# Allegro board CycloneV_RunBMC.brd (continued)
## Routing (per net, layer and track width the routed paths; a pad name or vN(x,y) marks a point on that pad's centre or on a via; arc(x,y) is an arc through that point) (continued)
FP_ID_BTN_N: length 37.2
  TOP w0.104: v1(52.58,3.7) 52.61,3.7 52.94,3.37 52.94,2.9 52.93,2.88 JT3.199
  TOP w0.127: UT7.T12 v1(30.78,16.81)
  L3-SIG w0.076: v1(52.58,3.7) 52.28,3.7 52.09,3.51 52.09,2.95 51.76,2.62 49.13,2.62 48.98,2.77 48.98,3.9 49.17,4.1 49.17,6.28 45.56,9.89 45.56,11.69 44.37,12.88 41.65,12.88 41.32,13.21 39.39,13.21 39.19,13.01 39.19,12.62 39.01,12.44 36.21,12.44 35.92,12.72 35.92,14.75 35.1,15.58 31.34,15.58 31.2,15.72 31.2,16.39 v1(30.78,16.81)
  L3-SIG w0.089: v1(30.78,16.81) 30.74,16.81
FP_ID_LED_N: length 16
  TOP w0.089: UT7.AH2 v1(39.58,9.61)
  BOTTOM w0.089: 33.63,7.65 33.63,8.15 33.86,8.39 34.18,8.39 34.43,8.63 34.43,8.95 34.63,9.16 38.12,9.16 38.12,9.16 39.13,9.16 v1(39.58,9.61)
  BOTTOM w0.112: 33.63,7.65 33.63,7.12 33.34,6.83 32.14,6.83 32.05,6.74 32.05,6.05 32.21,5.89 RB179.2 32.53,5.81 32.53,5.03 31.54,4.04 31.54,2.95 31.68,2.81 JT3.122
FP_LED_STATUS_AMBER_N: length 28.4
  TOP w0.127: UT7.T13 v1(30.78,17.61)
  L5-SIG w0.076: v1(30.78,17.61) 31.18,18.01 31.79,18.01 31.97,17.84 31.97,16.52 32.23,16.26 32.23,15.83 31.18,14.79 31.18,13.14 29.48,11.44 29.48,7.04 28.32,5.88 28.32,4.86 28.68,4.49 28.69,4.49 28.9,4.28 28.9,3.18 29.32,2.76 30.08,2.76 30.27,2.95 30.27,3.49 30.57,3.79 31.3,3.79 32.16,4.65 32.58,4.65 v1(32.73,4.5)
  BOTTOM w0.112: JT3.124 32.18,2.8 32.35,2.98 32.35,3.63 32.36,3.63 32.36,4.13 v1(32.73,4.5) 32.73,4.86 32.96,5.09 RB182.2
FP_LED_STATUS_GREEN_N: length 10.3
  TOP w0.127: v1(40.36,9.63) UT7.AH3
  BOTTOM w0.089: v1(40.36,9.63) 40.43,9.56 RB154.2
  BOTTOM w0.112: RB154.2 40.43,8.62 40.56,8.49 41.75,8.49 42.13,8.11 42.13,4.91 42.46,4.58 42.46,2.93 42.68,2.71 JT3.158
FP_NMI_BTN_N: length 29.1
  TOP w0.104: v1(51.27,3.85) 51.63,3.49 51.63,3.08 51.43,2.88 JT3.193
  TOP w0.127: UT7.AF11 v1(38.78,16.01)
  L3-SIG w0.076: v1(38.78,16.01) 39.14,15.64 39.89,15.64 40.2,15.95 40.72,15.95 42.44,14.23 44.57,14.23 45.28,13.52 49.93,13.52 50.31,13.9 51.56,13.9 51.86,13.59 51.86,12.91 52.46,12.31 52.46,9.07 52.47,9.06 52.47,9.05 52.52,9 52.52,6.58 52.28,6.35 52.28,5.6 52.1,5.42 51.2,5.42 50.89,5.11 50.89,4.22 v1(51.27,3.85)
FP_PWR_BTN_N: length 13.9
  TOP w0.127: UT7.AF5 v1(38.78,11.21)
  BOTTOM w0.112: v1(38.78,11.21) 39.16,10.83 39.16,10.1 39.27,9.99 40.79,9.99 40.8,9.98 41.88,9.98 42.37,9.49 42.37,5.87 43.55,4.69 43.55,3.7 43.33,3.47 43.33,2.82 43.18,2.68 JT3.160
FP_RST_BTN_N: length 22.6
  TOP w0.104: v1(31.97,3.79) 31.7,3.52 31.57,3.52 31.43,3.37 JT3.121
  TOP w0.127: UT7.AF10 v1(38.78,15.21)
  L8-SIG w0.076: v1(31.97,3.79) 31.97,4.18 32,4.2 32,4.83 32.73,5.57 32.73,6.18 33,6.44 35.82,6.44 37.39,8.02 40.04,8.02 41.35,9.33 41.35,10.53 39.97,11.91 39.97,12.98 39.16,13.79 39.16,14.83 v1(38.78,15.21)
IRQ_BMC_PCH_NMI: length 24.4
  TOP w0.127: UT7.C14 v1(19.58,18.41)
  L8-SIG w0.076: v1(19.58,18.41) 19.17,18.81 16.54,18.81 14.83,17.1 14.83,16.62 12.08,13.87 12.08,10.24 11.4,9.56 11.4,7.75 10.29,6.64 10.29,5.02 11.01,4.3 11.14,4.3 v1(11.37,4.07)
  BOTTOM w0.112: v1(11.37,4.07) 11.45,4.07 11.78,3.74 11.78,3.18 11.68,3.08 JT3.42
IRQ_BMC_PCH_SCI_LPC_R_N: length 30.5
  TOP w0.127: UT7.J16 v1(24.38,20.81)
  L8-SIG w0.076: v1(12.36,3.85) 12.08,4.12 11.88,4.33 11.88,5.24 12.27,5.63 12.27,6.85 11.88,7.24 11.88,9.33 12.58,10.03 12.58,11.88 13.73,13.04 14.65,13.04 15.44,13.82 15.44,14.81 17.85,17.23 20.59,17.23 21.79,18.43 21.79,18.9 23.25,20.37 23.94,20.37 v1(24.38,20.81)
  BOTTOM w0.112: JT3.44 12.18,2.98 12.09,3.07 12.09,3.58 v1(12.36,3.85)
  BOTTOM w0.114: v1(12.36,3.85) 12.08,4.12 11.83,4.38 11.83,5.03 12.17,5.37 12.25,5.37 12.36,5.48 RB73.2
IRQ_BMC_PCH_SMI_LPC_N: length 30.6
  TOP w0.127: UT7.AF23 v1(38.78,26.41)
  L5-SIG w0.076: v1(41.6,7.49) 41.89,7.78 41.89,10.38 41.34,10.93 41.34,11.21 41.95,11.82 41.95,13.9 41.32,14.53 41.32,18.93 42.42,20.03 42.42,21.44 41.52,22.33 41.52,24.34 40.62,25.25 40.23,25.25 40.02,25.46 40.02,25.9 39.87,26.04 39.15,26.04 v1(38.78,26.41)
  BOTTOM w0.089: RB72.2 39.49,27.03 39.22,26.76 39.13,26.76 v1(38.78,26.41)
  BOTTOM w0.112: v1(41.6,7.49) 40.98,6.87 40.98,5.29 41.11,5.15 41.11,5.15 41.9,4.36 41.9,3.11 41.68,2.88 JT3.154
IRQ_L_PIRQA_N_E_ALERT0_N_BMC: length 18.2
  TOP w0.104: JT3.171 45.93,3.27 45.33,3.87 44.75,3.87 v1(44.73,3.89)
  TOP w0.127: UT7.AA4 v1(34.78,10.41)
  L3-SIG w0.076: v1(34.78,10.41) 35.17,10.01 35.17,8.72 35.5,8.39 36.04,8.39 36.85,7.57 40.94,7.57 41.23,7.86 41.76,7.86 42.05,7.57 42.05,6.47 42.67,5.85 43.02,5.85 44.25,4.62 44.25,4.37 v1(44.73,3.89)
IRQ_NMI_EVENT_N: length 23.3
  TOP w0.127: UT7.B14 v1(18.78,18.41)
  L3-SIG w0.076: v1(12.35,4.41) 12.61,4.67 12.61,4.7 12.74,4.83 12.74,4.88 13.71,5.85 13.71,6.99 14.11,7.39 14.11,8.84 14.03,8.92 14.03,11.4 13.81,11.62 13.81,12.78 13.98,12.95 13.98,14.43 14.17,14.62 14.17,14.99 13.88,15.28 13.88,17.48 14.13,17.73 14.68,17.73 14.83,17.58 15.31,17.58 15.72,17.99 18.36,17.99 v1(18.78,18.41)
  BOTTOM w0.112: v1(12.35,4.41) 12.74,4.02 12.74,4.02 12.75,4.01 12.75,3.69 12.93,3.51 12.93,3.5 12.93,3.5 12.93,3.18 12.68,2.92 JT3.46
IRQ_SMB_INTERNAL_ALERT_N: length 21.8
  TOP w0.114: 19.58,21.61 v1(19.58,21.62)
  TOP w0.127: UT7.C17 19.58,21.61
  L3-SIG w0.076: v1(19.58,21.62) 19.17,22.03 19.17,22.54 18.92,22.79 18.43,22.79 18.21,22.56 18.21,22.38 17.74,21.92 16.93,21.92 16.17,21.16 16.17,19.87 15.89,19.58 14.01,19.58 12.13,17.71 12.13,16.36 10.31,14.53 10.31,13.57 v1(9.9,13.16)
  BOTTOM w0.114: v1(9.9,13.16) 9.63,12.89 9.63,12.81 8.87,12.06 RB140.1 ; RB88.1 18.39,21.97 19.23,21.97 v1(19.58,21.62)
IRQ_SMB_INTERNAL_ALERT_R_N: length 9.1
  TOP w0.104: EUT2.6 7.63,10.12 8.08,10.57 8.08,10.83 8.2,10.96 v1(8.2,10.98) 8.48,11.25 8.49,11.25 8.78,11.54 10.18,11.54 10.31,11.66 10.94,11.66 11.25,11.36 12.31,11.36 12.61,11.66 13.54,11.66 13.81,11.93 EUT1.22
  BOTTOM w0.112: RB140.2 7.7,11.08 8.1,11.08 v1(8.2,10.98)
IRQ_SMI_ACTIVE_N: length 50.6
  TOP w0.127: v1(41.03,27.48) 41.03,27.22 40.88,27.08 40.33,27.08 40.2,27.21 39.58,27.21 UT7.AG24
  L8-SIG w0.076: v1(15.39,5.82) 15.39,5.83 15.71,6.16 15.71,9.1 16.12,9.51 17.24,9.51 17.52,9.78 17.52,13.85 18.51,14.84 18.94,14.84 18.94,14.84 19.78,14.84 19.96,15.02 19.96,15.32 20.21,15.58 20.57,15.58 20.77,15.77 20.77,16.54 23.31,19.08 25.65,19.08 26.38,19.82 26.38,23.09 27.22,23.93 27.22,24.16 27.5,24.45 27.73,24.45 28.01,24.73 28.01,25.05 28.44,25.48 34.89,25.48 35.38,25.96 35.71,25.96 36.54,26.8 40.3,26.8 40.6,27.1 40.65,27.1 41.02,27.48 v1(41.03,27.48)
  BOTTOM w0.112: JT3.70 18.68,4.18 17.77,5.09 17.05,5.09 16.31,5.82 v1(15.39,5.82)
IRQ_SML0_ALERT_N: length 34.8
  TOP w0.127: UT7.B18 v1(18.78,22.41)
  L3-SIG w0.076: v1(17.37,4.7) 17.37,3.67 16.94,3.24 16.94,3.23 16.38,2.67 12.68,2.67 11.97,3.38 11.97,5.41 11.99,5.42 11.99,7.84 12.5,8.34 12.5,12.13 13.15,12.78 13.15,14.1 13,14.25 13,15.22 13.43,15.65 13.43,17.91 14.55,19.03 16.12,19.03 16.83,19.74 16.83,20.17 17.77,21.11 18.23,21.11 18.38,21.27 18.38,22.01 v1(18.78,22.41)
  BOTTOM w0.112: v1(17.37,4.7) 17.77,4.3 17.77,2.95 17.65,2.83 17.65,1.61 JT3.66
  BOTTOM w0.114: v1(18.78,22.41) 18.81,22.44 RB95.1
IRQ_SML1_PMBUS_ALERT_N: length 39.4
  TOP w0.089: UT7.AG15 39.53,19.26 40.25,19.26 40.38,19.39
  TOP w0.104: 40.38,19.39 41.22,20.22 RT57.1
  TOP w0.114: v1(41.5,20.86) 41.36,20.72 RT57.1
  L8-SIG w0.076: v1(19.5,4.88) 19.5,5.4 20.24,6.14 21.02,6.14 21.07,6.19 21.52,6.64 22,6.64 23.39,8.03 23.39,8.87 24.5,9.99 24.66,9.99 24.82,10.15 24.82,10.56 25.04,10.79 29.27,10.79 29.56,11.08 29.56,11.3 30.71,12.45 31.41,12.45 32.15,13.19 32.47,13.19 32.74,13.46 32.74,13.83 32.94,14.03 33.31,14.03 33.54,14.26 33.54,14.65 33.72,14.84 34.12,14.84 34.34,15.06 34.34,15.63 34.59,15.88 35.2,15.88 35.9,16.58 35.9,17.37 36.49,17.96 37.02,17.96 37.03,17.97 40.87,17.97 41.5,18.6 v1(41.5,20.86)
  BOTTOM w0.112: JT3.74 19.68,2.88 19.93,3.13 19.93,4.46 v1(19.5,4.88)
ISENSE_P3V3_C: length 0.5
  BOTTOM w0.112: RB161.2 CB210.1
ISENSE_P3V3_N: length 1.2
  TOP w0.104: RT101.2 8.22,9.17 7.93,9.47 EUT2.5
ISENSE_P3V3_P: length 1.3
  TOP w0.104: EUT2.4 6.71,8.65 6.97,8.39 v1(7.08,8.39)
  BOTTOM w0.112: v1(7.08,8.39) 7.03,8.34 6.51,8.34 CB210.2
ISENSE_P12V_C: length 0.6
  TOP w0.104: CT25.1 RT134.2
ISENSE_P12V_N: length 3
  TOP w0.104: v1(4.79,7.87) 4.79,8 4.58,8.21 EUT2.1
  BOTTOM w0.112: RB171.2 5.19,6.37 4.79,6.76 v1(4.79,7.87)
ISENSE_P12V_P: length 2.7
  TOP w0.104: CT25.2 3.45,7.37 3.27,7.55 3.27,8.62 3.77,9.11 EUT2.16
JTAG_C5_FPGA_TCK: length 60.2
  TOP w0.127: UT7.AB5 v1(35.58,11.21)
  L3-SIG w0.076: v1(59.15,47.4) 59.15,47.03 58.56,46.44 49.5,46.44 48.74,45.67 v1(46.35,45.67)
  L5-SIG w0.076: v1(35.58,11.21) 36.04,11.21 36.77,11.94 36.77,18.85 37.54,19.62 37.54,23.58 38.34,24.38 38.34,26.48 38.66,26.8 43.25,26.8 45.61,29.16 45.61,30.4 46.55,31.35 46.55,36.05 46.11,36.49 46.11,37.99 46.75,38.64 46.75,44.88 46.35,45.29 v1(46.35,45.67)
  BOTTOM w0.112: v1(59.15,47.4) 59.15,47.84 59,47.99 CB22.1 RB48.1 57.78,47.99 57.7,47.91 57.7,47.24 57.63,47.17 U12.4
JTAG_C5_FPGA_TDI: length 54.2
  TOP w0.127: UT7.W10 v1(33.18,15.21)
  L8-SIG w0.076: v1(33.18,15.21) 34.08,16.11 34.79,16.11 35.43,16.74 35.43,17.64 36.57,18.78 40.79,18.78 41.04,19.03 41.04,21.03 41.43,21.42 44.18,21.42 45.92,23.16 45.92,28.17 47.01,29.27 47.01,31.27 49.07,33.33 49.07,41.76 50.36,43.06 60.19,43.06 61.03,43.9 v1(61.03,45.09)
  BOTTOM w0.112: 59.78,44.21 U12.9 RB49.2 CB33.1 60.69,44.72 61.03,45.07 v1(61.03,45.09)
JTAG_C5_FPGA_TDO: length 46.5
  L8-SIG w0.076: v1(42.87,17.63) 42.87,18.34 43.73,19.21 43.73,20.3 46.2,22.76 46.2,28.05 49.37,31.22 49.37,39.44 50.91,40.98 58.28,40.98 v1(58.57,40.7)
  BOTTOM w0.112: v1(58.57,40.7) 58.72,40.85 58.72,42.3 58.48,42.54 CT7.1 58.13,43.3 U12.12 ; v1(42.87,17.63) 42.6,17.36 42.6,17.2 42.5,17.1 40.3,17.1 40,17.4 38.29,17.4 38.11,17.23 36.75,17.23 36.47,16.95 36.47,15.13 RB123.1
JTAG_C5_FPGA_TDO_R: length 2.5
  TOP w0.127: UT7.Y9 33.96,14.43 v1(33.98,14.43)
  BOTTOM w0.089: RB123.2 35.36,14.84 34.38,14.84 33.98,14.43 v1(33.98,14.43)
JTAG_C5_FPGA_TDO_SW: length 11.4
  L10-SIG w0.076: v1(52.43,45.62) 52.43,46 52.35,46.08 51.71,46.08 51.5,45.88 51.5,43.67 52.62,42.55 v1(57.19,42.55)
  BOTTOM w0.112: UB2.3 v1(52.43,45.62) ; U12.14 57.13,42.61 v1(57.19,42.55)
JTAG_C5_FPGA_TMS: length 65
  TOP w0.127: UT7.AC7 v1(36.38,12.81)
  L3-SIG w0.076: v1(51.15,12.66) 48.76,12.66 48.38,13.04 48.19,13.04 48.06,12.91 48.06,12.6 47.82,12.36 47.47,12.36 47.25,12.58 47.25,12.71 46.92,13.04 45,13.04 44.52,13.52 42.16,13.52 41.26,14.42 40.27,14.42 39.86,14.01 36.99,14.01 36.77,13.8 36.77,13.2 v1(36.38,12.81)
  L8-SIG w0.076: v1(51.15,12.66) 51.48,12.66 51.66,12.83 51.66,14.1 50.6,15.16 50.6,21.2 50.15,21.65 50.15,24.95 49.93,25.18 49.93,30.3 50.87,31.23 50.87,37.67 51.25,38.05 59.07,38.05 61.18,40.16 v1(61.18,40.82)
  BOTTOM w0.112: v1(61.18,40.82) 61.18,41.71 61.56,42.09 61.56,44.94 61.56,44.94 61.56,45.26 61.56,45.26 61.56,46.11 61.37,46.3 CB23.1 RB46.2 60.46,46.82 59.2,46.82 59.13,46.75 U12.7
JTAG_HDR_SW_TCK: length 2.3
  TOP w0.104: v1(56.61,47.38) 56.61,47 56.74,46.87 RB52.2
  BOTTOM w0.112: U12.2 56.63,47.31 56.61,47.33 v1(56.61,47.38)
JTAG_HDR_SW_TMS: length 14.7
  L5-SIG w0.076: v1(52.37,39.48) 53.82,40.92 54.62,40.92 55.11,41.42 55.11,44.23 55.63,44.74 55.63,47.81 55.86,48.05 57.82,48.05 58.08,47.78 v1(58.08,47.38)
  BOTTOM w0.112: v1(52.37,39.48) 52.58,39.69 RB26.2 ; U12.5 58.13,47.33 v1(58.08,47.38)
JTAG_HDR_TCK: length 12.6
  TOP w0.104: J8.1 50.26,41.31 50.56,41 55.87,41 56.45,41.57 56.45,42.59 56.15,42.88 56.15,43.97 56.34,44.16 RB51.1 RB52.1
JTAG_HDR_TDI: length 2.7
  TOP w0.104: J8.9 55.34,41.64 v1(55.54,41.43)
  BOTTOM w0.112: v1(55.54,41.43) 55.54,40.72 RB22.1
JTAG_HDR_TDO: length 9.8
  TOP w0.104: v1(51.66,41.51) 51.53,41.64 J8.3
  L5-SIG w0.076: v1(51.9,45.6) 51.9,41.95 51.66,41.71 v1(51.66,41.51)
  BOTTOM w0.112: v1(51.9,45.6) 51.9,45.98 51.86,46.02 51.86,48.09 52.01,48.24 UB2.4 ; CB51.1 v1(51.66,41.51)
JTAG_HDR_TMS: length 3.6
  TOP w0.104: v1(52.77,41.43) 52.8,41.46 J8.5
  BOTTOM w0.112: v1(52.77,41.43) 53.03,41.18 RB26.1 RB28.1
JTAG_HPS_TCK: length 33.1
  TOP w0.104: v1(11.07,40.11) 11.3,40.11 11.85,40.67 11.85,40.74 12.58,41.47 RT1.1 12.64,41.76 12.89,42.01 J4.4
  TOP w0.127: UT7.K19 25.18,23.21 v1(25.16,23.21)
  L10-SIG w0.076: v1(25.16,23.21) 25.16,23.38 24.78,23.75 24.78,24.09 24.48,24.39 23.26,24.39 23.18,24.31 21.86,24.31 21.56,24.62 21.56,24.91 21.27,25.2 20.95,25.2 20.8,25.35 20.8,27.29 20.44,27.64 17.21,27.64 15.11,29.75 15.11,33.3 13.76,34.65 13.76,39.45 13.28,39.93 13.1,39.93 12.31,40.72 11.68,40.72 v1(11.07,40.11)
JTAG_HPS_TDI: length 28.1
  TOP w0.104: 10.48,41.46 10.35,41.59 J4.8 ; 10.48,41.46 10.71,41.46 v1(11.04,41.79) ; 10.48,41.46 RT3.2
  TOP w0.127: UT7.D22 v1(20.38,25.61)
  L10-SIG w0.076: v1(20.38,25.61) 20,25.99 17.57,25.99 16.86,26.69 16.84,26.69 14.4,29.14 13.84,29.14 13.35,29.62 13.35,31.83 13.15,32.03 12.85,32.03 12.39,32.49 12.39,32.75 12.16,32.97 9.72,32.97 9.47,33.23 9.47,33.74 9.59,33.86 9.59,38.11 10,38.51 10,40.75 v1(11.04,41.79)
JTAG_HPS_TDO: length 23.8
  TOP w0.104: v1(11.04,41.23) 11.26,41.45 RT4.2 11.54,41.79 11.62,41.87 J4.6
  TOP w0.127: v1(17.87,26.45) 17.91,26.41 18.77,26.41 UT7.B23
  L10-SIG w0.076: v1(11.04,41.23) 10.99,41.23 10.43,40.67 10.43,34.13 10.62,33.94 11.47,33.94 11.95,33.46 12.64,33.46 13.56,32.54 13.56,29.83 13.79,29.6 14.37,29.6 17.52,26.45 v1(17.87,26.45)
JTAG_HPS_TMS: length 23.9
  TOP w0.104: v1(11.98,39.76) 12.92,39.76 13.54,40.38 13.54,41.19 13.71,41.36 14.29,41.36 14.38,41.45 RT5.2 14.54,42.1 14.16,42.48 J4.2
  TOP w0.127: UT7.C23 v1(19.58,26.41)
  L10-SIG w0.076: v1(19.58,26.41) 19.13,26.85 17.54,26.85 14.83,29.57 14.83,33 13.57,34.26 13.57,38.17 v1(11.98,39.76)
JTAG_M10_MASTER_TCK: length 1
  BOTTOM w0.112: U12.3 57.13,47.49 RB54.2
JTAG_M10_MASTER_TCK_R: length 19.4
  TOP w0.127: UT4.K11 v1(53.39,33.53)
  L5-SIG w0.076: v1(53.39,33.53) 52.9,34.02 52.9,39.15 53.74,39.99 55.39,39.99 56.51,41.1 56.51,43.31 56.08,43.74 v1(56.08,47.5)
  BOTTOM w0.112: v1(56.08,47.5) 56.08,48.08 56.53,48.53 57.16,48.53 RB54.1
JTAG_M10_MASTER_TDI: length 19.1
  L3-SIG w0.076: v1(51.38,39.5) 51.81,39.93 51.81,40.85 51.96,41 55.67,41 56.41,40.26 59.43,40.26 v1(59.81,40.65)
  BOTTOM w0.112: v1(51.38,39.5) 50.92,39.05 50.92,35.21 50.77,35.06 50.09,35.06 RB70.2 ; v1(59.81,40.65) 59.58,40.87 59.58,41.07 59.58,41.07 59.58,42.29 59.13,42.74 U12.10
JTAG_M10_MASTER_TDI_R: length 1.6
  TOP w0.127: UT4.K14 v1(50.42,33.55)
  BOTTOM w0.112: v1(50.42,33.55) 49.62,33.55 RB70.1
JTAG_M10_MASTER_TDO: length 12.1
  TOP w0.127: UT4.L11 v1(53.39,34.52)
  L5-SIG w0.076: v1(57.19,41.43) 57.19,38.94 56.28,38.03 55.11,38.03 54.81,37.72 54.81,36.2 54.58,35.97 54.2,35.97 53.99,35.77 53.99,35.13 v1(53.39,34.52)
  BOTTOM w0.112: U12.13 57.63,41.87 v1(57.19,41.43)
JTAG_M10_MASTER_TMS: length 27.4
  L5-SIG w0.076: v1(52.42,37.57) 51.8,38.19 51.8,39.96 51.67,40.09 50.95,40.09 50.59,40.44 50.59,47.86 51.17,48.44 58.26,48.44 58.62,48.09 v1(58.62,47.38)
  BOTTOM w0.112: U12.6 58.63,47.36 v1(58.62,47.38) ; RB55.2 52.75,32.11 52.93,32.29 52.93,36.71 52.42,37.22 v1(52.42,37.57)
JTAG_M10_MASTER_TMS_R: length 1.2
  TOP w0.127: UT4.K12 v1(52.42,33.56)
  BOTTOM w0.112: RB55.1 52.42,33.02 v1(52.42,33.56)
JTAG_M10_TCK: length 15.5
  TOP w0.104: RB51.2 RB53.1 CB55.1 58.21,42.07 58.72,41.56 58.72,41.15 v1(59.2,40.67) ; UT4.H3 v1(62.29,32.43)
  L10-SIG w0.076: v1(62.29,32.43) 62.76,32.89 62.76,36.48 61.69,37.55 60.78,37.55 59.2,39.12 v1(59.2,40.67)
JTAG_M10_TDI: length 18.5
  TOP w0.104: UT4.G1 63.93,31.07 64.51,31.07 64.64,31.2 v1(64.81,31.2)
  L10-SIG w0.076: v1(56.33,39.5) 57.98,39.5 60.88,36.61 60.88,31.4 61.41,30.87 64.48,30.87 v1(64.81,31.2)
  BOTTOM w0.112: v1(56.33,39.5) 56.03,39.81 RB22.2 55.42,39.65 RB24.2 CB2.1
JTAG_M10_TDO: length 28
  TOP w0.104: RT48.2 v1(67.37,31.65)
  L10-SIG w0.076: v1(52.43,45.09) 52.43,44.65 53.43,43.64 64.15,43.64 64.83,42.96 64.83,35.9 65.55,35.18 65.55,32.37 66.26,31.65 v1(67.37,31.65)
  BOTTOM w0.112: UB3.4 v1(52.43,45.09)
JTAG_M10_TDO_BYPASS: length 6.1
  L5-SIG w0.076: v1(53.96,41.48) 53.96,44.97 53.71,45.21 v1(53.71,45.6)
  BOTTOM w0.112: UB3.1 53.73,41.71 v1(53.96,41.48) ; UB2.1 53.74,46.45 53.74,45.62 v1(53.71,45.6)
JTAG_M10_TDO_R: length 2.2
  TOP w0.104: UT4.H1 65.58,32.02 RT48.1
JTAG_M10_TDO_SW: length 10.6
  L10-SIG w0.076: v1(59.18,41.26) 58.51,41.26 58.26,41 52.65,41 v1(52.22,41.43)
  BOTTOM w0.112: v1(59.18,41.26) 59.2,41.28 59.2,42.17 58.63,42.74 U12.11 ; UB3.3 52.43,41.65 v1(52.22,41.43)
JTAG_M10_TMS: length 18.1
  TOP w0.104: UT4.H2 v1(63.35,32.49)
  L10-SIG w0.076: v1(63.35,32.49) 62.85,31.98 62.05,31.98 61.83,32.2 61.83,36.77 61.46,37.14 60.8,37.14 57.93,40.01 54.86,40.01 v1(54.35,39.5)
  BOTTOM w0.112: CB17.1 RB33.2 53.64,39.59 RB28.2 54.16,39.69 v1(54.35,39.5)
LED_AMBER_C: length 1.6
  TOP w0.104: DST2.C 67.66,36.95 67.13,36.42 67.13,36.1 RT32.1
LED_AMBER_R: length 1.7
  TOP w0.104: RT32.2 66.74,34.14 66.82,34.07 v1(66.82,34.02)
  BOTTOM w0.112: QB1.6 v1(66.82,34.02)
LED_GREEN_C: length 1.5
  TOP w0.104: RT31.1 66.01,36.86 DST1.2
LED_GREEN_R: length 2.9
  TOP w0.104: v1(64.92,34.57) 65.31,34.57 65.57,34.83 RT31.2
  BOTTOM w0.112: QB1.3 65.52,33.41 64.92,34.01 v1(64.92,34.57)
LPC_CLK_24M_66M_LPC0_ESPI_BMC: length 28.8
  TOP w0.104: v1(48.33,3.66) 48.2,3.66 47.89,3.35 47.89,1.62 JT3.179
  TOP w0.127: UT7.U9 31.58,14.41 v1(31.58,13.61)
  L3-SIG w0.076: v1(48.33,3.66) 48.33,6.77 47.26,7.84 46.22,7.84 45.57,8.49 44.31,8.49 42.68,10.12 42.68,11.2 42,11.87 40.56,11.87 39.55,10.86 36.56,10.86 35.87,11.55 35.55,11.55 35.17,11.93 35.17,12.45 34.46,13.16 34.46,13.6 34.06,14 31.97,14 v1(31.58,13.61)
LPC_LAD0_ESPI_IO0_BMC: length 22.1
  TOP w0.104: v1(44.7,4.55) 44.34,4.19 44.34,3.68 44.51,3.51 45.18,3.51 45.43,3.26 JT3.169
  TOP w0.127: UT7.W8 v1(33.17,13.62)
  L3-SIG w0.076: v1(44.7,4.55) 44.53,4.72 44.51,4.72 43.1,6.13 42.79,6.13 42.39,6.53 42.39,7.58 41.63,8.34 40.2,8.34 39.87,8.01 36.69,8.01 35.96,8.73 35.96,9.72 35.67,10.01 35.48,10.01 35.17,10.32 35.17,10.51 34.85,10.83 34.67,10.83 34.38,11.11 34.38,11.3 33.17,12.51 v1(33.17,13.62)
LPC_LAD1_ESPI_IO1_BMC: length 18.6
  TOP w0.104: v1(45.02,3.12) 44.93,3.03 JT3.167
  TOP w0.127: UT7.Y4 v1(33.98,10.41)
  L3-SIG w0.076: v1(45.02,3.12) 44.6,3.12 43.66,4.07 43.66,4.45 42.84,5.26 42.56,5.26 41.44,6.39 41.44,6.39 41.29,6.53 36.87,6.53 36.06,7.35 33.9,7.35 33.63,7.62 33.63,10.06 v1(33.98,10.41)
LPC_LAD2_ESPI_IO2_BMC: length 18.1
  TOP w0.104: JT3.177 47.43,3.35 46.71,4.07 v1(46.32,4.07)
  TOP w0.127: UT7.AB4 v1(35.58,10.41)
  L3-SIG w0.076: v1(46.32,4.07) 45.95,4.07 45.09,4.93 45.03,4.93 45.02,4.93 44.6,4.93 43.2,6.33 43.02,6.33 42.62,6.73 42.62,7.65 41.64,8.63 39.96,8.63 39.79,8.46 37.46,8.46 36.8,9.12 36.8,9.68 36.07,10.41 v1(35.58,10.41)
LPC_LAD3_ESPI_IO3_BMC: length 28.3
  TOP w0.104: JT3.175 46.93,2.94 v1(46.81,3.06)
  TOP w0.127: UT7.T8 v1(30.78,13.61)
  L3-SIG w0.076: v1(30.78,13.61) 30.43,13.27 30.43,7.46 31.21,6.69 31.62,6.69 32.82,5.48 37.49,5.48 41.01,5.48 42.06,4.44 42.06,2.78 42.65,2.19 45.94,2.19 v1(46.81,3.06)
LPC_LFRAME_N_ESPI_CS0_N_BMC: length 19.9
  TOP w0.104: v1(46.41,3.52) 46.4,3.51 46.4,1.6 JT3.173
  TOP w0.127: UT7.Y5 v1(33.98,11.21)
  L3-SIG w0.076: v1(46.41,3.52) 46.04,3.52 46.03,3.52 44.57,3.52 43.9,4.19 43.9,4.64 42.97,5.57 42.55,5.57 41.52,6.59 41.52,6.59 41.4,6.71 41.4,6.71 40.79,7.32 36.77,7.32 36.25,7.84 36.25,7.84 36.01,8.08 34.61,8.08 34.33,8.36 34.33,10.86 v1(33.98,11.21)
NC_EMMC<0>: length 0.6
  BOTTOM w0.127: UB4.A1 13.13,41.61 v1(13.13,41.48)
NC_EMMC<1>: length 0.6
  BOTTOM w0.127: UB4.A2 12.08,41.57 v1(12.03,41.57)
NC_EMMC<2>: length 2.3
  BOTTOM w0.112: v1(5.49,39.67) 5.49,40.05 5.53,40.1 5.53,41.53 5.48,41.58 UB4.A9
NC_EMMC<3>: length 0.7
  BOTTOM w0.112: UB4.A10 4.2,41.69 v1(3.9,41.69)
NC_EMMC<4>: length 0.5
  BOTTOM w0.127: v1(14,40.99) 13.5,40.99 UB4.B1
NC_EMMC<5>: length 3.1
  BOTTOM w0.127: v1(4.01,38.03) 4.01,39.78 4.48,40.26 UB4.B10
NC_EMMC<6>: length 0.7
  BOTTOM w0.127: UB4.T1 v1(13.98,26.47)
NC_EMMC<7>: length 0.7
  BOTTOM w0.127: UB4.T10 v1(3.99,26.47)
NC_EMMC<8>: length 0.7
  BOTTOM w0.127: UB4.U1 v1(13.98,25.47)
NC_EMMC<9>: length 0.7
  BOTTOM w0.127: UB4.U2 v1(12.98,25.47)
NC_EMMC<10>: length 0.9
  BOTTOM w0.127: v1(6.27,25.66) 5.85,25.66 5.8,25.66 UB4.U9
NC_EMMC<11>: length 0.7
  BOTTOM w0.127: v1(3.91,25.58) 4.31,25.97 UB4.U10
NC_EMMC_RFU<0>: length 0.7
  BOTTOM w0.112: v1(13.06,39.38) 12.66,38.97 UB4.D2
NC_EMMC_RFU<1>: length 0.7
  BOTTOM w0.112: v1(11.98,39.2) 11.95,39.2 11.94,39.2 11.59,39.2 11.49,39.09 UB4.D3
NC_EMMC_RFU<2>: length 2
  BOTTOM w0.112: v1(11.98,40.29) 11.71,40.02 11.53,40.02 UB4.D4
NC_EMMC_RFU<3>: length 1.2
  BOTTOM w0.112: v1(9.62,39.86) 9.89,39.59 9.89,39.38 UB4.D5
NC_EMMC_RFU<4>: length 3.2
  BOTTOM w0.127: UB4.D6 8.81,39.3 8.81,40.93 v1(8.02,41.71)
NC_EMMC_RFU<5>: length 0.7
  BOTTOM w0.127: UB4.D7 v1(7.01,38.5)
NC_EMMC_RFU<6>: length 0.6
  BOTTOM w0.127: UB4.D8 v1(6.05,38.54)
NC_EMMC_RFU<7>: length 0.6
  BOTTOM w0.127: v1(4.92,38.79) 5.3,38.79 UB4.D9
NC_EMMC_RFU<8>: length 0.6
  BOTTOM w0.112: v1(13.07,38.08) 12.9,38.08 12.79,37.97 UB4.E2
NC_EMMC_RFU<9>: length 0.6
  BOTTOM w0.112: UB4.E3 v1(11.9,38.38)
NC_EMMC_RFU<10>: length 0.6
  BOTTOM w0.112: UB4.E5 9.49,37.79 v1(9.2,37.5)
NC_EMMC_RFU<11>: length 0.7
  BOTTOM w0.127: UB4.E6 v1(7.98,38.47)
NC_EMMC_RFU<12>: length 0.7
  BOTTOM w0.127: UB4.E7 v1(7,37.49)
NC_EMMC_RFU<13>: length 2.6
  BOTTOM w0.127: UB4.E8 6.06,37.97 5.65,38.38 5.32,38.38 4.91,37.97 4.84,37.97 v1(4.39,37.52)
NC_EMMC_RFU<14>: length 0.7
  BOTTOM w0.127: UB4.E9 v1(5,37.49)
NC_EMMC_RFU<15>: length 0.7
  BOTTOM w0.127: UB4.H4 v1(10.98,35.47)
NC_EMMC_RFU<17>: length 0.7
  BOTTOM w0.127: UB4.H6 v1(8.01,34.5)
NC_EMMC_RFU<18>: length 0.7
  BOTTOM w0.127: UB4.H7 v1(7.95,35.44)
NC_EMMC_RFU<19>: length 0.7
  BOTTOM w0.127: UB4.J2 12.6,33.97 v1(13.01,34.38)
NC_EMMC_RFU<20>: length 0.7
  BOTTOM w0.127: UB4.J3 v1(11.98,34.47)
NC_EMMC_RFU<21>: length 0.7
  BOTTOM w0.127: UB4.J4 v1(10.98,34.47)
NC_EMMC_RFU<22>: length 1.7
  BOTTOM w0.127: v1(10,34.45) 9.42,34.45 8.95,33.97 UB4.J6
NC_EMMC_RFU<23>: length 0.7
  BOTTOM w0.127: UB4.J7 v1(6.99,34.47)
NC_EMMC_RFU<24>: length 0.7
  BOTTOM w0.127: UB4.J8 v1(5.99,34.47)
NC_EMMC_RFU<25>: length 0.7
  BOTTOM w0.127: UB4.J9 v1(4.99,34.47)
NC_EMMC_RFU<26>: length 0.7
  BOTTOM w0.127: UB4.K4 v1(10.98,32.47)
NC_EMMC_RFU<28>: length 0.7
  BOTTOM w0.127: UB4.K7 v1(6.99,32.47)
NC_EMMC_RFU<30>: length 0.7
  BOTTOM w0.127: UB4.L6 v1(7.98,31.47)
NC_EMMC_RFU<31>: length 0.7
  BOTTOM w0.127: UB4.M2 v1(12.98,30.47)
NC_EMMC_RFU<32>: length 0.7
  BOTTOM w0.127: UB4.M3 v1(11.98,30.47)
NC_EMMC_RFU<33>: length 0.7
  BOTTOM w0.112: UB4.M6 v1(8.02,30.51)
NC_EMMC_RFU<34>: length 0.6
  BOTTOM w0.127: UB4.M8 v1(6.04,30.53)
NC_EMMC_RFU<35>: length 1.4
  BOTTOM w0.112: UB4.M9 4.84,30.97 v1(4.29,31.53)
NC_EMMC_RFU<36>: length 0.7
  BOTTOM w0.127: UB4.N4 v1(10.98,29.47)
NC_EMMC_RFU<37>: length 0.7
  BOTTOM w0.127: UB4.N5 v1(9.98,29.47)
NC_EMMC_RFU<38>: length 0.7
  BOTTOM w0.112: UB4.N6 v1(8.01,29.49)
NC_EMMC_RFU<40>: length 0.7
  BOTTOM w0.127: UB4.P4 v1(10.98,28.47)
NC_EMMC_RFU<41>: length 0.7
  BOTTOM w0.127: v1(7.99,28.5) 7.96,28.5 UB4.P7
NC_FAN_PWM_START0: length 3.1
  TOP w0.104: EUT3.25 13.68,11.08 13.65,11.11 v1(13.65,11.25)
  BOTTOM w0.112: v1(13.65,11.25) 13.94,10.96 RB150.1 14.69,10.64 14.81,10.76 RB149.2
NC_M10_VREFB7: length 0.7
  TOP w0.127: UT4.A15 v1(49.38,24.52)
Net_26: length 0.8
  TOP w0.127: 50.88,28.02 v1(50.3,28.6)
NL_C5_M10_RX_CLK: length 24.8
  TOP w0.104: UT4.P14 50.39,38.51 v1(48.13,38.51)
  TOP w0.114: v1(44.72,25.68) 44.67,25.68 43.55,26.81 UT7.AH24
  L8-SIG w0.076: v1(48.13,38.51) 48.81,37.83 48.81,33.48 47.39,32.06 45.43,32.06 45.13,31.76 45.13,31.44 45.33,31.24 45.33,27.4 44.92,26.98 44.62,26.98 44.34,26.69 44.34,26.07 v1(44.72,25.68)
NL_C5_M10_RX_DAT: length 17.6
  TOP w0.114: UT7.AG26 39.58,28.81 40.3,28.81 40.63,29.14 v1(40.94,29.14)
  TOP w0.127: UT4.P15 49.36,37.5 47.82,37.5 47.68,37.64 46.92,37.64 v1(46.78,37.5)
  L10-SIG w0.076: v1(46.78,37.5) 46.48,37.5 45.27,36.29 45.27,32.81 42.56,30.1 40.94,30.1 40.67,29.84 40.67,29.4 v1(40.94,29.14)
NL_C5_M10_TX_CLK: length 24
  TOP w0.104: UT4.N14 50.88,37.02 50.34,36.48 48.22,36.48 47.94,36.76 v1(47.19,36.76)
  TOP w0.114: v1(44.14,25.53) 44.06,25.61 44.06,25.71 43.33,26.45 40.42,26.45 UT7.AH23
  L8-SIG w0.076: v1(44.14,25.53) 43.81,25.86 43.81,26.69 44.19,27.07 44.19,31.46 45.01,32.29 45.32,32.29 45.41,32.38 47.4,32.38 48.01,32.99 48.01,36.65 47.9,36.76 v1(47.19,36.76)
NL_C5_M10_TX_DAT: length 17.9
  TOP w0.104: UT4.N16 47.66,37.02 v1(47.44,37.24)
  TOP w0.127: UT7.AG23 v1(39.58,26.41)
  L10-SIG w0.076: v1(47.44,37.24) 47.08,37.24 46.42,36.58 46.12,36.58 45.54,36 45.54,32.77 43.15,30.38 43.15,29.04 42.84,28.73 40.56,28.73 39.58,27.75 v1(39.58,26.41)
P2E_PCH_BMC_RX_C_DN: length 4.8
  TOP w0.089: 36.77,7.65 36.85,7.73 36.85,8.33 UT7.AD1
  TOP w0.091: CT30.1 38.6,5.49 38.3,5.79 37.2,5.79 36.82,6.17 36.82,6.71 36.75,6.79 36.75,7.02 36.82,7.09 36.82,7.3 36.75,7.37 36.75,7.62 36.77,7.65
P2E_PCH_BMC_RX_C_DP: length 5
  TOP w0.089: 37.13,7.65 37.13,7.65 37.13,8.67 36.78,9.02 UT7.AD2
  TOP w0.091: CT29.1 38.54,6.28 38.37,6.1 37.33,6.1 37.13,6.3 37.13,7.65
P2E_PCH_BMC_RX_DN: length 6.3
  TOP w0.091: CT30.2 39.91,5.57 40.24,5.57 40.33,5.66 40.33,5.87 40.43,5.97 40.91,5.97 41.32,5.57 41.32,4.84 41.83,4.34 41.83,3.18 41.76,3.11 41.76,3.11 41.55,2.89 41.55,1.69 JT3.153
P2E_PCH_BMC_RX_DP: length 6.5
  TOP w0.091: CT29.2 39.86,6.28 41.04,6.28 41.63,5.7 41.63,4.97 42.13,4.46 42.13,3.06 42.06,2.99 42.06,2.98 41.85,2.77 41.85,1.62 41.9,1.57 JT3.155
P2E_PCH_BMC_TX_DN: length 9
  TOP w0.089: UT7.AF1 38.34,8.41 38.14,8.21 38.14,7.87 38.23,7.78 38.4,7.78 38.55,7.93 38.73,7.93 38.91,7.75 38.91,7.65
  TOP w0.091: v1(38.75,6.94) 38.77,6.94 38.91,7.07 38.91,7.24 38.81,7.34 38.81,7.47 38.91,7.58 38.91,7.65 ; JT3.147 39.93,2.88 40.02,2.97 40.02,3.51 39.77,3.76 39.77,4.4 40.09,4.73 v1(40.28,4.91)
  BOTTOM w0.091: v1(38.75,6.94) 38.75,6.86 38.97,6.65 38.97,6.54 40.35,5.16 40.35,5 40.28,4.93 40.28,4.91 v1(40.28,4.91)
P2E_PCH_BMC_TX_DP: length 9.2
  TOP w0.089: UT7.AF2 38.8,8.78 38.8,8.12 39.21,7.71 39.21,7.65
  TOP w0.091: JT3.149 40.43,2.88 40.33,2.98 40.33,3.64 40.07,3.89 40.07,4.27 40.33,4.52 40.45,4.52 40.79,4.86 40.79,4.86 v1(40.81,4.87) ; v1(39.31,6.95) 39.21,7.04 39.21,7.65
  BOTTOM w0.091: v1(39.31,6.95) 39.35,6.91 39.35,6.84 39.28,6.77 39.28,6.67 40.66,5.29 40.66,5.06 40.81,4.91 v1(40.81,4.87)
PD_BMC_DDR3_DQS5_P: length 3.8
  TOP w0.127: U4.C7 v1(37.75,35.16)
  BOTTOM w0.119: RB56.1 39.59,33.68 39.34,33.93 39.34,34.43 38.88,34.89 38.02,34.89 v1(37.75,35.16)
PD_C5_RREF_TL: length 2.4
  TOP w0.127: UT7.B1 v1(18.78,8.01)
  BOTTOM w0.089: v1(18.78,8.01) 17.62,8.01
  BOTTOM w0.112: RB167.2 17.41,7.86 17.56,8.01 17.62,8.01
PD_CLK_50OHM_TERM: length 4.2
  BOTTOM w0.112: RB187.1 31.05,5.25 31.05,5.03 31.07,5.02 31.07,4.54 30.87,4.35 30.87,4.21 30.18,3.52 JT3.116
PD_FAN_FREQ_START: length 2.7
  TOP w0.104: v1(10.62,10.41) 11.17,9.87 EUT3.1
  BOTTOM w0.112: RB147.2 9.97,10.41 v1(10.62,10.41) 11.18,10.41 RB146.1
PD_FAN_PWM_START1: length 2.4
  TOP w0.104: EUT3.26 13.28,11.1 13.12,11.26 v1(13.05,11.26)
  BOTTOM w0.112: RB151.1 v1(13.05,11.26) 13.02,11.23 12.59,11.23 12.57,11.21 RB144.2
PD_FAN_SPIN_START: length 2.8
  TOP w0.104: v1(10.58,9.88) 11,9.47 EUT3.2
  BOTTOM w0.112: RB153.2 10.31,9.68 10.5,9.88 v1(10.58,9.88) 10.67,9.88 10.86,9.68 RB152.1
PD_FRU_A1: length 2.4
  BOTTOM w0.112: UB5.2 45.87,21.21 45.74,21.34 45.74,21.82 45.92,22 R1A11.1
PD_HPS_RZQ_0: length 4.8
  TOP w0.127: UT7.D25 21.18,27.21 v1(21.18,27.19)
  BOTTOM w0.089: v1(21.18,27.19) 20.91,26.92 20.89,26.92 20.77,26.8 17.72,26.8
  BOTTOM w0.112: RB74.1 17.46,26.92 17.6,26.92 17.72,26.8
PD_PCA9554_A0: length 1.6
  TOP w0.104: EUT1.18 v1(10.91,13.39)
  BOTTOM w0.112: RB132.1 11.57,13.39 v1(10.91,13.39)
PD_PCA9554_A1: length 1.5
  TOP w0.104: EUT1.23 14.31,12.08 14.24,12.02 v1(14.24,12.01)
  BOTTOM w0.112: RB137.1 14.24,12.46 v1(14.24,12.01)
PD_PCA9554_A2: length 1.6
  TOP w0.104: EUT1.24 14.81,12.03 v1(14.8,12.02)
  BOTTOM w0.112: v1(14.8,12.02) 14.8,12.13 RB136.1
PD_QS3VH257QG_OE_N: length 0.8
  BOTTOM w0.112: U12.15 56.64,43.29 RT10.1
PD_SI5351_EN_N: length 1.2
  TOP w0.104: R5C8.1 46.22,10.37 46.66,9.93 EU5C1.7
PD_SI5351_SSEN: length 2
  TOP w0.104: EU5C1.6 47.07,11.17 46.86,11.38 46.28,11.38 R5C14.1
PD_SPI_EEPROM_WP: length 4.8
  BOTTOM w0.112: R436.1 45.59,10.65 45.71,10.78 45.71,12.19 45.62,12.29 R2A17.2 45.18,12.65 45.28,12.75 45.51,12.75 45.87,13.11 UB5.7
PD_TELEMETRY_ADDR: length 1.8
  TOP w0.104: EUT2.14 2.94,10.77 2.76,10.95 v1(2.75,10.95)
  BOTTOM w0.112: RB145.1 3.04,11.21 2.79,10.95 v1(2.75,10.95)
PD_USBPHY_PCH_RBIAS: length 1.3
  TOP w0.104: R7A55.1 60.75,11.74 60.42,12.07 U8A6.24
PD_USBPHY_USB2B_RBIAS: length 1.4
  TOP w0.104: EU12.24 63.24,19.82 v1(63.32,19.89)
  BOTTOM w0.112: v1(63.32,19.89) 63.82,19.89 R397.1
PD_V_M_DDR3_DQU<0>: length 3.8
  TOP w0.127: U4.D7 v1(37.75,35.96)
  BOTTOM w0.112: RB63.1 37.37,33 37.37,35.55 37.75,35.93 v1(37.75,35.96)
PD_V_M_DDR3_DQU<1>: length 3.3
  TOP w0.127: U4.C3 v1(41.75,35.16)
  BOTTOM w0.112: RB61.1 41.12,34.91 41.37,35.16 v1(41.75,35.16)
PD_V_M_DDR3_DQU<2>: length 4
  TOP w0.127: U4.C8 v1(36.95,35.16)
  BOTTOM w0.112: v1(36.95,35.16) 36.54,34.76 36.54,34.17 36.34,33.97 35.96,33.97 35.73,33.74 35.73,33.25 36.05,32.94 RB65.1
PD_V_M_DDR3_DQU<3>: length 3
  TOP w0.127: U4.C2 v1(42.55,35.16)
  BOTTOM w0.112: v1(42.55,35.16) 42.15,34.76 RB59.1
PD_V_M_DDR3_DQU<4>: length 1.3
  TOP w0.127: U4.A7 v1(37.75,33.56)
  BOTTOM w0.112: RB62.1 38.02,33.29 v1(37.75,33.56)
PD_V_M_DDR3_DQU<5>: length 1.3
  TOP w0.127: U4.A2 v1(42.55,33.56)
  BOTTOM w0.112: RB58.1 42.77,33.34 v1(42.55,33.56)
PD_V_M_DDR3_DQU<6>: length 2.3
  TOP w0.127: U4.B8 v1(36.95,34.36)
  BOTTOM w0.112: v1(36.95,34.36) 36.95,34.17 36.57,33.78 36.57,33.36 36.92,33 RB64.1
PD_V_M_DDR3_DQU<7>: length 1.2
  TOP w0.127: U4.A3 v1(41.75,33.56)
  BOTTOM w0.112: v1(41.75,33.56) 41.62,33.44 RB60.1
PECI_SMC: length 4.8
  BOTTOM w0.112: RB180.1 RB181.2 29.61,4.93 29.18,4.5 JT3.112
PECI_SMC_IN: length 1.7
  BOTTOM w0.112: RB90.1 42.75,23.03 42.6,23.19 U7.3
PECI_SMC_IN_LVC33: length 5.8
  TOP w0.089: 40.73,21.16 UT7.AH16
  TOP w0.104: v1(42,24.64) 40.94,23.58 40.94,21.37 40.73,21.16
  BOTTOM w0.112: RB77.2 41.92,24.64 v1(42,24.64)
PECI_SMC_OUT_B: length 1.8
  BOTTOM w0.112: RB168.1 29.03,7.24 28.83,7.44 U8.4
PECI_SMC_OUT_N: length 18.2
  TOP w0.104: RT115.1 28.66,5.97 v1(28.98,5.65)
  TOP w0.127: UT7.AA15 v1(34.78,20.01)
  L5-SIG w0.076: v1(28.98,5.65) 30.42,7.1 30.42,7.6 31.18,8.36 31.18,11.54 32.78,13.14 32.78,16.13 33.06,16.41 33.37,16.41 33.6,16.64 33.6,18.83 v1(34.78,20.01)
PECI_SMC_OUT_N_R1: length 3.4
  TOP w0.104: v1(27,5.79) 27,5.89 27.33,6.23 RT115.2
  BOTTOM w0.112: U8.1 26.81,6.14 27,5.95 v1(27,5.79)
  BOTTOM w0.114: RB169.2 25.37,6.15 25.39,6.14 U8.1
PECI_SMC_R: length 1.8
  BOTTOM w0.112: RB77.1 41.61,25.84 42.39,25.84 42.6,26.05 U7.4
PECI_SMC_S_R: length 30.7
  L5-SIG w0.076: v1(42.3,10.87) 42.3,11.26 42.21,11.35 42.21,14.02 41.6,14.62 41.6,18.83 42.67,19.89 42.67,21.85 v1(42.18,22.33)
  BOTTOM w0.089: 30.92,7.65 32.63,7.65 32.81,7.83 32.81,9.84 32.96,9.99 33.39,9.99 33.55,10.14 33.55,10.62 33.78,10.85 36.21,10.85 36.92,11.56 39.01,11.56 39.8,10.78 40.73,10.78
  BOTTOM w0.112: 40.73,10.78 41.29,10.78 41.52,10.55 41.98,10.55 v1(42.3,10.87) ; RB90.2 42.37,22.14 v1(42.18,22.33) ; RB181.1 29.61,6.68 29.72,6.79 30.4,6.79 30.51,6.9 RB168.2 30.92,7.65
PU_BATTERY_SENSE_EN: length 4.2
  BOTTOM w0.112: JT3.156 42.18,4.44 41.55,5.07 RB178.2
PU_BMC_DDR3_DQS5_N: length 3.3
  TOP w0.127: U4.B7 v1(37.75,34.36)
  BOTTOM w0.119: v1(37.75,34.36) 38.02,34.63 38.77,34.63 39.08,34.32 39.08,33.93 38.83,33.68 RB57.2
PU_FAN_MAX_A0: length 3
  TOP w0.104: EUT3.4 11.26,8.67 11.2,8.73 v1(10.57,8.73)
  BOTTOM w0.112: RB163.1 11.17,8.16 10.6,8.73 v1(10.57,8.73) 10.54,8.73 9.98,8.16 RB164.2
PU_FAN_MAX_A1: length 2.9
  TOP w0.104: v1(10.6,9.32) 10.85,9.07 EUT3.3
  BOTTOM w0.112: RB159.1 11.14,8.92 10.74,9.32 v1(10.6,9.32) 10.38,9.32 9.98,8.92 RB160.2
PU_FAN_PWM6: length 4.1
  TOP w0.104: RT122.2 8.71,5 8.71,3.1 8.93,2.88 JT3.31
PU_FAN_PWM7: length 4
  BOTTOM w0.112: RB185.2 9.72,4.95 9.72,1.62 JT3.34
PU_FAN_WD_START: length 3.7
  TOP w0.104: EUT3.5 11.25,8.27 11.16,8.18 v1(10.58,8.18)
  BOTTOM w0.112: RB166.2 10.25,7.4 10.38,7.52 10.38,7.99 v1(10.58,8.18) 10.74,8.02 10.74,7.54 10.88,7.4 RB165.1
PU_FRU_A0: length 2.2
  BOTTOM w0.112: R1A9.1 44.93,21.6 45.22,21.3 UB5.1
PU_JTAG_HPS_TRST_N: length 2.9
  TOP w0.127: UT7.C22 v1(19.58,25.61)
  BOTTOM w0.112: RB78.2 17.53,25.2 19.17,25.2 v1(19.58,25.61)
PU_M10_CONF_DONE: length 1.2
  TOP w0.127: UT4.E7 v1(58.38,28.52)
  BOTTOM w0.112: RB96.1 58.35,28.49 v1(58.38,28.52)
PU_M10_CONFIG_N: length 1.4
  TOP w0.127: UT4.E8 v1(57.38,28.52)
  BOTTOM w0.112: v1(57.38,28.52) 56.96,28.1 RB97.1
PU_M10_STATUS_N: length 2.5
  TOP w0.127: UT4.F7 v1(58.38,29.52)
  BOTTOM w0.112: v1(58.38,29.52) 57.85,28.99 57.24,28.99 56.99,28.73 RB91.1
PU_MAX_FSD_N: length 3.3
  TOP w0.114: R393.2 10.2,10.82 11.44,10.82 11.75,11.12 12.64,11.12 12.88,10.88 EUT3.27
PU_P1V1_AUX_EN: length 0.9
  TOP w0.104: RT63.2 13.4,17.98 RT67.1
PU_P1V2_AUX_EN: length 0.9
  BOTTOM w0.112: RB127.2 RB128.1
PU_P1V8_AUX_EN: length 0.9
  BOTTOM w0.254: RB141.1 RB142.2
PU_TELEMETRY_ENA: length 4
  TOP w0.127: RT94.2 7.78,13.49 6.21,13.49 5.23,12.52 EUT2.11
PU_TELEMETRY_SHTDN: length 3.4
  TOP w0.127: EUT2.10 5.88,12.52 6.48,13.11 7.27,13.11 RT96.2
PU_TMP75_8_A0: length 3.5
  TOP w0.104: RT109.2 RT103.1 44.48,7.88 44.04,8.33 43.42,8.33 43.29,8.46 UT10.7
PU_TMP75_8_A1: length 2.9
  TOP w0.104: RT105.2 RT104.1 42.51,8.33 42.64,8.45 UT10.6
PU_TMP75_8_A2: length 4.1
  TOP w0.104: UT10.5 41.99,8.46 42.06,8.39 42.06,6.34 RT130.1 42.14,6.25 42.78,6.25 RT131.2
PU_TRACE_GND_DETECT: length 4
  TOP w0.104: v1(10.64,45.34) 10.33,45.65 9.21,45.65 9.08,45.78 J4.9
  BOTTOM w0.112: RB27.2 v1(10.64,45.34)
PU_V_M_BMC_DDR3_DM_5: length 1.5
  TOP w0.127: U4.D3 v1(41.75,35.96)
  BOTTOM w0.112: v1(41.75,35.96) 41.46,36.25 RB50.2
PWRGD_BMC_AUX_VRS: length 121.3
  TOP w0.104: v1(21.3,4.86) 21.3,4.17 21.43,4.04 JT3.81
  L5-SIG w0.076: v1(2,44.66) 3.03,43.63 3.03,32.54 3.52,32.05 3.52,28.46 3.77,28.22 3.77,28.19 5.51,26.45 5.51,25.48 6.58,24.4 6.58,22.32 5.72,21.45 5.72,15.45 4.13,13.86 4.13,7.32 4.2,7.25 4.2,7.24 5.72,5.73 5.72,3.98 5.47,3.73 5.42,3.73 5.05,3.36 5.05,2.32 5.45,1.91 14.42,1.91 15.21,2.7 15.21,3.51 15.82,4.12 20.56,4.12 v1(21.3,4.86)
  L8-SIG w0.076: v1(2,44.66) 2.58,44.66 3.6,45.68 3.6,47.5 4.41,48.32 48.71,48.32 v1(49.66,49.27)
  BOTTOM w0.112: v1(49.66,49.27) 49.65,49.26 R8F12.2 ; v1(2,44.66) 2.69,43.97 R8L2.1
PWRGD_CPU0_LVC3: length 30
  TOP w0.127: UT7.AG20 v1(39.58,24.01)
  L5-SIG w0.076: 36.9,7.65 36.9,8.24 37.26,8.59 37.26,8.79 37.54,9.08 37.54,11.34 38.37,12.17 38.37,18.8 39.14,19.57 39.14,23.57 v1(39.58,24.01)
  L5-SIG w0.254: v1(31.51,4.91) 31.24,4.91 30.98,5.16 30.98,5.75 31.29,6.05 32.38,6.05 32.75,6.42 33.76,6.42 33.98,6.2 36.09,6.2 36.9,7.02 36.9,7.65
  BOTTOM w0.254: v1(31.51,4.91) 31.51,4.45 31.27,4.21 31.27,4.21 31.18,4.12 JT3.120
PWRGD_P0V75_AUX_R: length 2.7
  BOTTOM w0.254: R8F12.1 49.5,47.5 R8F7.2 48.84,47.45 C8F7.1 48.69,46.72 EU8F1.9
PWRGD_P1V1_AUX: length 20.8
  TOP w0.203: RT53.2 12.79,23.04 12.72,22.97 UT6.12
  TOP w0.254: v1(7.28,24.69) 7.13,24.54 RT51.1 ; RT53.2 13.3,23.59 13.8,24.08 ; 13.8,24.08 13.8,24.34 13.12,25.02 12.47,25.02 12.39,25.1 11.85,25.1 11.47,24.72 v1(11.47,24.26) ; 13.8,24.08 14,24.29 15.33,24.29 15.59,24.03 QT1.5
  TOP w0.508: RT62.1 6.13,18.89 6.14,18.9 v2(6.19,18.9)
  L10-SIG w0.381: v1(7.28,24.69) 7.21,24.62 7.21,22.15 6.19,21.14 v2(6.19,18.9)
  BOTTOM w0.254: v1(7.28,24.69) 7.74,24.69 7.97,24.92 10.81,24.92 v1(11.47,24.26)
PWRGD_P1V1_AUX_N: length 15.9
  TOP w0.254: v1(7.28,25.28) 8.73,25.28 9.34,24.67 10.88,24.67 11.7,25.48 11.73,25.48 12.24,25.99 14.5,25.99 14.83,26.32 RT45.2 ; v1(4.02,24.93) 3.64,24.54 RT50.1 ; RT39.1 15.98,27.13 15.78,26.93 15.63,26.93 15.4,26.7 15.22,26.7 15.02,26.5 RT45.2 ; RT45.2 15.06,26.27 15.06,25.3 QT1.3
  BOTTOM w0.254: v1(4.02,24.93) 4.08,24.93 4.54,25.38 4.69,25.38 4.87,25.2 6.46,25.2 6.53,25.28 v1(7.28,25.28)
PWRGD_P1V5_AUX: length 79.8
  TOP w0.254: UT5.12 5.05,22.65 5.05,23.97 4.98,24.03 RT52.2 4.98,24.53 v1(5.12,24.67)
  L8-SIG w0.254: v1(48.41,49.26) 47.76,48.61 4.29,48.61 4.28,48.6 2.46,48.6 1.39,47.53 1.39,34.88 2.41,33.86 2.41,32.62 1.97,32.19 1.52,32.19 0.86,31.53 0.86,25.86 2.56,24.16 4.63,24.16 5.12,24.66 v1(5.12,24.67)
  BOTTOM w0.254: v1(48.41,49.26) 48.41,48.8 48.13,48.52 R8F8.1
PWRGD_P1V8_PCH_AUX: length 133.6
  TOP w0.254: UT4.J14 v1(50.41,32.55) ; JT3.59 15.93,2.81 16.15,3.02 v1(16.15,3.31)
  L5-SIG w0.254: v1(16.15,3.31) 16.15,2.55 15,1.4 2.65,1.4 1.31,2.74 1.31,3.49 3.55,5.72 3.55,6.28 2.46,7.37 1.82,7.37 0.98,8.21 0.98,16.06 1.85,16.92 1.85,17.4 2.38,17.94 2.38,18.4 2.74,18.75 3.65,18.75 3.96,19.06 3.96,21.9 2.56,23.3 2.56,23.86 0.64,25.78 0.64,46.77 2.59,48.73 47.26,48.73 48.79,47.2 48.79,40.18 49.02,39.95 49.02,34.88 49.65,34.25 49.65,33.31 v1(50.41,32.55)
PWRGD_P2V5_AUX: length 1.9
  TOP w0.254: UT8.12 5.04,18.07 4.54,18.57 RT61.2
PWRGD_PS_PWROK_PLD_BMC: length 14.4
  TOP w0.104: v1(18.94,6.43) 18.67,6.16 18.67,4.49 20.43,2.73 JT3.77
  TOP w0.127: UT7.A8 v1(17.92,13.55)
  L3-SIG w0.076: v1(18.94,6.43) 18.94,6.91 18.38,7.47 18.38,11.49 18.26,11.61 17.77,11.61 17.62,11.77 17.62,13.25 v1(17.92,13.55)
PWRGD_SMC_AUX_VRS_R2: length 1.5
  BOTTOM w0.254: Q3L1.2 5.24,44.36 R8L2.2
RGMII_BMC_RMM4_MDC: length 69.4
  TOP w0.104: v1(16.81,11.05) 17.27,11.51 17.27,15.52 16.92,15.87 RT74.1
  L10-SIG w0.076: v1(16.81,11.05) 16.48,11.05 15.89,10.46 15.89,9.81 16.55,9.15 17.27,9.15 17.36,9.05 17.36,7.7 18.41,6.65 18.41,6.3 18.71,6.01 19.73,6.01 19.9,6.18 21.25,6.18 21.4,6.03 22.43,6.03 22.57,6.18 29.86,6.18 30.18,5.86 32.34,5.86 33.01,5.19 33.95,5.19 34.33,5.57 43,5.57 43.53,5.03 45.46,5.03 45.71,4.78 45.71,2.55 46.2,2.06 59.58,2.06 60.5,2.98 60.5,4.46 60.59,4.55 63.09,4.55 63.39,4.25 64.51,4.25 v1(64.65,4.38)
  BOTTOM w0.112: 64.99,5.32 RB189.1 ; 64.99,5.32 64.65,4.99 v1(64.65,4.38) ; 64.99,5.32 65.09,5.22 65.09,3.66 64.95,3.51 64.95,3.16 64.94,3.15 64.94,3.15 64.68,2.88 JT3.246
RGMII_BMC_RMM4_MDIO: length 71.3
  L3-SIG w0.076: v1(22.72,20.84) 23.16,20.4 28.62,20.4 29.05,19.97 30.22,19.97 31.46,21.21 31.77,21.21 32,21.44 32,21.71 32.24,21.95 38.96,21.95 39.24,21.67 39.24,21.32 39.46,21.09 40.81,21.09 41.12,21.39 44.11,21.39 44.47,21.04 46.41,21.04 47.57,19.88 53.37,19.88 54.4,20.91 55.95,20.91 57.85,22.81 64.66,22.81 65.08,22.4 65.08,16.83 66.27,15.64 66.27,12.44 66.97,11.74 67.58,11.74 68.18,11.14 68.18,9.42 68.01,9.25 v1(67.43,9.25)
  BOTTOM w0.089: RB103.1 22.69,20.81 v1(22.72,20.84)
  BOTTOM w0.112: v1(67.43,9.25) 66.97,8.79 66.64,8.79 66.16,8.31 66.16,6.96 65.93,6.73 65.93,6.72 65.89,6.68 65.89,5.6 65.76,5.47 65.76,5.47 65.73,5.44 65.72,5.44 65.64,5.35 65.58,5.35 RB188.1 65.4,5.17 65.4,3.62 65.22,3.45 65.22,1.62 JT3.248
RGMII_BMC_RMM4_R_MDC: length 2.5
  TOP w0.089: 17.62,17.25 UT7.A13
  TOP w0.104: RT74.2 17.13,16.76 17.62,17.25
RGMII_BMC_RMM4_R_MDIO: length 1.4
  TOP w0.127: UT7.E16 v1(21.18,20.81)
  BOTTOM w0.089: v1(21.18,20.81) 21.61,20.37 21.63,20.37 21.8,20.21 RB103.2
RGMII_BMC_RMM4_R_TXD_0: length 76.8
  TOP w0.104: v1(62.43,6.2) 62.22,6.41 61.95,6.41 61.84,6.3 RT128.2
  TOP w0.127: UT7.A16 v1(17.82,20.41)
  L10-SIG w0.076: v1(62.43,6.2) 63.47,6.2 65.03,4.65 65.03,3.16 63.26,1.4 41.95,1.4 40.48,2.88 40.48,3.49 38.96,5.01 34.64,5.01 33.39,3.76 33.39,3.49 32.28,2.37 20.57,2.37 16.6,6.33 16.6,6.43 15.46,7.58 15.46,10.64 15.64,10.83 15.64,12.25 15.59,12.3 15.59,14.28 15.84,14.53 15.84,17.01 15.6,17.26 15.6,17.73 16.72,18.85 17.9,18.85 18.26,19.21 18.26,19.98 v1(17.82,20.41)
RGMII_BMC_RMM4_R_TXD_1: length 64.4
  TOP w0.104: v1(63.98,7.44) 63.59,7.44 63.11,6.95 RT133.2
  TOP w0.127: UT7.J14 v1(24.38,18.41)
  L3-SIG w0.076: v1(63.98,7.44) 64.46,7.92 64.46,11.56 65.17,12.27 65.17,14.79 64.99,14.97 64.18,14.97 63.76,15.38 63.76,16.1 64.17,16.5 64.17,17.57 63.78,17.95 63.78,19.94 63.19,20.53 61.59,20.53 60.92,19.86 58.36,19.86 58.25,19.75 58.25,18.71 58.16,18.62 57.98,18.62 57.9,18.71 57.9,19.75 57.81,19.84 57.63,19.84 57.54,19.75 57.54,18.71 57.45,18.62 57.27,18.62 57.18,18.71 57.18,19.75 57.1,19.84 56.92,19.84 56.83,19.75 56.83,18.71 56.74,18.62 56.56,18.62 56.47,18.71 56.47,19.75 56.38,19.84 55.55,19.84 55.1,19.39 54.33,19.39 54,19.06 46.84,19.06 46.53,19.37 44.13,19.37 43.91,19.59 41.22,19.59 41.01,19.39 32.33,19.39 32.17,19.23 31.31,19.23 31.04,18.97 24.94,18.97 v1(24.38,18.41)
RGMII_BMC_RMM4_R_TXD_2: length 76.4
  TOP w0.104: v1(63.98,6.9) RT129.2
  TOP w0.127: UT7.A15 17.91,19.61 17.89,19.63 v1(17.84,19.63)
  L10-SIG w0.076: v1(63.98,6.9) 63.98,6.53 65.24,5.26 65.24,3.07 63.21,1.05 42,1.05 40.21,2.84 40.21,3.42 38.88,4.75 38.8,4.77 37.75,4.77 37.1,4.12 34.06,4.12 33.62,3.69 33.62,3.38 32.35,2.11 20.49,2.11 17.52,5.08 17.12,5.08 16.29,5.9 16.02,5.9 15.74,6.18 15.74,6.99 15.18,7.55 15.18,10.67 15.39,10.88 15.39,12.04 15.03,12.4 15.03,17.52 16.64,19.13 17.76,19.13 17.84,19.22 v1(17.84,19.63)
RGMII_BMC_RMM4_R_TXD_3: length 71.9
  TOP w0.104: v1(65.42,6.89) 65.03,6.89 64.86,6.73 RT132.2
  TOP w0.127: UT7.D17 v1(20.38,21.61)
  L3-SIG w0.076: v1(20.38,21.61) 20.83,21.16 21.39,21.16 22.94,19.61 30.88,19.61 31.13,19.86 31.13,20.23 31.29,20.4 31.73,20.4 32.02,20.7 32.02,21.04 32.2,21.21 38.93,21.21 39.31,20.83 40.81,20.83 41.23,20.42 43.57,20.42 43.94,20.78 46.22,20.78 47.29,19.72 47.48,19.72 47.49,19.7 53.5,19.7 54.45,20.66 56.05,20.66 58.02,22.62 64.55,22.62 64.86,22.31 64.86,16.74 66.03,15.57 66.03,11.99 66.67,11.36 66.67,10.89 66.76,10.8 67.87,10.8 67.96,10.71 67.96,10.51 67.87,10.42 66.78,10.42 66.69,10.33 66.69,10.13 66.78,10.04 67.85,10.04 67.94,9.95 67.94,9.76 67.84,9.66 67.11,9.66 67.02,9.57 67.02,7.7 66.21,6.89 v1(65.42,6.89)
RGMII_BMC_RMM4_RX_CLK: length 65.5
  TOP w0.127: UT7.J12 v1(24.38,16.81)
  L3-SIG w0.076: v1(24.38,16.81) 24.03,17.16 24.03,18.55 24.66,19.18 31.01,19.18 31.26,19.44 32,19.44 32.18,19.61 40.89,19.61 41.17,19.89 43.86,19.89 44.21,20.25 46.02,20.25 46.98,19.28 53.87,19.28 54.68,20.1 60.83,20.1 61.49,20.76 63.32,20.76 63.98,20.1 63.98,18.19 64.41,17.76 64.41,16.34 63.98,15.91 63.98,15.47 64.26,15.19 65.12,15.19 65.45,14.86 65.45,10.75 64.74,10.04 64.74,5.17 v1(66.04,3.87)
  BOTTOM w0.112: v1(66.04,3.87) 66.04,3.87 65.89,3.72 65.88,3.72 65.58,3.41 65.58,2.99 65.68,2.88 JT3.250
RGMII_BMC_RMM4_RX_CTRL: length 63.5
  TOP w0.127: UT7.J13 v1(24.38,17.61)
  L3-SIG w0.076: v1(63.85,4.73) 63.6,4.98 63.6,11.91 63.44,12.07 60.19,12.07 60.01,12.25 60.01,17.11 59.92,17.2 59.65,17.2 59.56,17.11 59.56,15.59 59.47,15.5 59.29,15.5 59.2,15.59 59.2,17.09 59.11,17.18 58.93,17.18 58.85,17.09 58.85,15.59 58.76,15.5 58.58,15.5 58.49,15.59 58.49,17.11 58.4,17.2 57.24,17.2 55.75,18.69 54.58,18.69 54.43,18.85 46.63,18.85 46.35,19.13 43.3,19.13 42.9,18.74 41.73,18.74 41.31,19.16 32.53,19.16 32.37,18.99 31.38,18.99 31.14,18.76 29.64,18.76 28.9,18.01 24.78,18.01 v1(24.38,17.61)
  BOTTOM w0.112: JT3.242 63.68,2.88 63.85,3.06 v1(63.85,4.73)
RGMII_BMC_RMM4_RXD_0: length 75.4
  TOP w0.104: v1(60.98,3.55) 60.98,2.94 60.93,2.88 JT3.231
  TOP w0.127: v1(17.77,18.45) 17.95,18.45 18.31,18.81 UT7.A14
  L10-SIG w0.076: v1(60.98,3.55) 60.98,2.77 59.89,1.68 45.17,1.68 45.08,1.77 45.08,2.61 44.99,2.7 44.81,2.7 44.72,2.61 44.72,1.77 44.63,1.68 44.46,1.68 44.37,1.77 44.37,2.61 44.28,2.7 44.1,2.7 44.01,2.61 44.01,1.77 43.92,1.68 43.74,1.68 43.66,1.77 43.66,2.61 43.57,2.7 43.39,2.7 43.3,2.61 43.3,1.77 43.21,1.68 43.03,1.68 42.94,1.77 42.94,2.6 42.87,2.67 42.67,2.67 42.59,2.6 42.59,1.77 42.5,1.68 42.28,1.68 41.95,2.01 41.95,4.91 41.55,5.31 34.46,5.31 34.05,4.91 32.51,4.91 31.39,3.79 31.39,3.38 30.73,2.73 21.58,2.73 20.54,3.76 19.5,3.76 16.96,6.3 16.96,7.3 16.53,7.73 15.94,7.73 15.67,8 15.67,10.55 15.93,10.81 15.93,11.55 16.45,12.07 16.45,12.96 16.17,13.24 16.17,16.19 17.54,17.56 17.54,18.22 v1(17.77,18.45)
RGMII_BMC_RMM4_RXD_1: length 63
  TOP w0.104: v1(62.5,5.19) 61.93,4.61 JT3.235
  TOP w0.114: UT7.A11 v1(18.79,16.82)
  L3-SIG w0.076: v1(62.5,5.19) 62.88,5.19 63.39,5.69 63.39,10.12 62.91,10.59 62.03,10.59 61.36,11.26 58.36,11.26 58.02,11.6 58.02,12.03 57.82,12.24 57.82,16.15 55.46,18.5 54.44,18.5 54.32,18.62 45.08,18.62 44.83,18.87 43.36,18.87 43.01,18.52 41.5,18.52 41.07,18.95 32.71,18.95 32.52,18.77 31.45,18.77 31.21,18.53 31.21,18.22 31.01,18.01 30.6,18.01 30.35,17.76 30.35,17.48 30.04,17.18 29.41,17.18 28.59,16.36 23.44,16.36 22.62,17.18 19.15,17.18 v1(18.79,16.82)
RGMII_BMC_RMM4_RXD_2: length 68.2
  TOP w0.104: JT3.243 63.93,4.2 64.43,4.71 64.43,6.77 65.59,7.93 v1(65.7,7.93)
  TOP w0.127: UT7.C15 v1(19.58,20.01)
  L3-SIG w0.076: v1(65.7,7.93) 66.59,8.82 66.59,9.63 66.25,9.98 66.25,11.21 65.73,11.73 65.73,15.57 64.61,16.69 64.61,17.99 64.24,18.36 64.24,20.19 63.44,20.99 61.41,20.99 60.78,20.35 54.58,20.35 53.74,19.51 47.11,19.51 46.15,20.48 43.94,20.48 43.61,20.15 41.04,20.15 40.79,20.4 32.51,20.4 31.75,19.64 31.18,19.64 30.93,19.39 20.2,19.39 v1(19.58,20.01)
RGMII_BMC_RMM4_RXD_3: length 65.6
  TOP w0.104: v1(64.64,3.85) 64.95,3.54 64.95,2.9 64.93,2.88 JT3.247
  TOP w0.127: UT7.A9 18.74,15.17 18.76,15.17 v1(18.79,15.2)
  L3-SIG w0.076: v1(64.64,3.85) 63.74,3.85 63.02,4.57 62.21,4.57 62.03,4.75 62.03,5.49 62.16,5.62 62.81,5.62 63.16,5.97 63.16,10.04 62.82,10.38 61.5,10.38 60.92,10.95 58.04,10.95 57.8,11.18 57.8,11.89 56.97,12.73 56.97,15.6 56.65,15.91 51.52,15.91 49.65,17.79 45.48,17.79 44.72,18.55 43.53,18.55 43.25,18.27 40.91,18.27 40.42,18.76 32.93,18.76 32.78,18.61 32.78,18.32 32.45,17.99 31.44,17.99 31.16,17.71 31.16,17.35 31.03,17.23 30.68,17.23 30.42,16.97 30.42,16.62 30.22,16.41 29.58,16.41 28.77,15.6 23.29,15.6 23.02,15.86 23.02,16.1 22.71,16.41 19.42,16.41 19.17,16.16 19.17,15.58 v1(18.79,15.2)
RGMII_BMC_RMM4_TX_CLK: length 2.7
  BOTTOM w0.112: RB186.1 63.19,3.87 63.32,3.74 63.32,2.98 63.18,2.84 JT3.240
RGMII_BMC_RMM4_TX_CTRL: length 4
  BOTTOM w0.112: JT3.244 64.18,3.58 64.23,3.63 64.23,4.57 64.26,4.59 64.26,5.17 RB183.1
RGMII_BMC_RMM4_TX_R_CLK: length 71.9
  TOP w0.127: UT7.J15 v1(24.38,20.01)
  L5-SIG w0.076: v1(24.38,20.01) 23.43,19.06 22.4,19.06 21.52,18.18 21.52,6.01 21.81,5.72 21.81,4.58 21.18,3.94 21.18,1.4 22.03,0.55 36.07,0.55 37.25,1.73 37.25,3.93 37.87,4.55 38.76,4.55 39.86,3.45 39.86,1.65 40.96,0.55 59.49,0.55 62.33,3.38 v1(62.33,4.17)
  BOTTOM w0.112: v1(62.33,4.17) 62.6,4.44 62.6,4.7 62.85,4.95 63.01,4.95 63.16,5.1 RB186.2
RGMII_BMC_RMM4_TX_R_CTRL: length 68.6
  TOP w0.089: 17.62,16.46 18.36,17.21 UT7.A12
  TOP w0.104: 17.62,16.46 17.54,16.39 17.54,11.25 16.79,10.5 v1(16.78,10.5)
  L10-SIG w0.076: v1(16.78,10.5) 17.63,9.65 17.63,7.8 18.15,7.27 19.17,7.27 20.01,6.43 21.31,6.43 21.49,6.25 22.34,6.25 22.52,6.43 30.02,6.43 30.37,6.08 32.53,6.08 33.14,5.47 33.93,5.47 34.26,5.8 44.27,5.8 44.44,5.97 45.43,5.97 45.95,5.46 45.95,2.84 46.48,2.32 58.79,2.32 59.35,2.88 59.35,4.98 60.95,6.58 62.55,6.58 63.82,7.85 65.09,7.85 65.55,7.4 v1(65.6,7.4)
  L10-SIG w0.089: v1(16.78,10.5) 16.81,10.5
  BOTTOM w0.112: RB183.2 65.13,7.4 v1(65.6,7.4)
RGMII_BMC_RMM4_TXD_0: length 4.7
  TOP w0.104: RT128.1 61.41,5.36 60.86,4.82 60.86,4.77 60.32,4.22 60.32,2.99 60.43,2.88 JT3.229
RGMII_BMC_RMM4_TXD_1: length 4.1
  TOP w0.104: RT133.1 63.11,4.38 62.38,3.65 62.38,2.94 62.43,2.88 JT3.237
RGMII_BMC_RMM4_TXD_2: length 4.1
  TOP w0.104: JT3.241 63.43,4.85 RT129.1
RGMII_BMC_RMM4_TXD_3: length 4.1
  TOP w0.104: JT3.249 65.43,2.88 65.38,2.93 65.38,4.36 64.86,4.88 RT132.1
RMII_BMC_NIC_TX_EN: length 4.7
  BOTTOM w0.112: RB184.2 58.6,5.55 59.38,4.78 59.38,3.08 59.18,2.88 JT3.224
RMII_BMC_NIC_TX_R_EN: length 29.1
  TOP w0.127: UT7.AH5 40.05,11.61 40.68,10.98 40.68,10.65 v1(40.96,10.37)
  L3-SIG w0.076: v1(58.64,3.71) 59.01,3.35 59.01,3.05 59,3.05 59,3.01 57.95,1.96 48.33,1.96 47.59,2.7 47.59,3.82 46.6,4.81 46.45,4.81 46.06,5.2 46.06,5.87 46.22,6.03 46.22,6.81 45.26,7.77 44.09,7.77 41.56,10.3 41.03,10.3 v1(40.96,10.37)
  BOTTOM w0.112: RB184.1 57.71,5.45 57.8,5.36 58.26,5.36 58.64,4.98 v1(58.64,3.71)
RMII_BMC_NIC_TXD_0: length 33.7
  L3-SIG w0.076: v1(61.51,3.87) 61.51,4.12 60.01,5.62 57.57,5.62 57.23,5.28 56.41,5.28 55.95,5.74 55.95,6.25 55.33,6.87 55.33,11.3 55.64,11.61 55.64,14.4 54.84,15.2 51.14,15.2 49.22,17.13 45.38,17.13 45.03,16.78 43.95,16.78 v1(43.61,17.12)
  BOTTOM w0.112: v1(61.51,3.87) 61.61,3.87 61.94,3.54 61.94,3.1 61.68,2.84 JT3.234 ; RB119.2 42.77,16.67 43.22,17.12 v1(43.61,17.12)
RMII_BMC_NIC_TXD_0_R: length 4.1
  TOP w0.127: UT7.AE12 v1(37.98,16.81)
  BOTTOM w0.089: v1(37.98,16.81) 38.32,17.15 38.63,17.15 38.63,17.16 38.92,17.16 39.72,17.16 39.73,17.15 39.82,17.15 40.3,16.67
  BOTTOM w0.104: 40.73,16.67 40.3,16.67
  BOTTOM w0.112: RB119.1 40.73,16.67
RMII_BMC_NIC_TXD_1: length 39.8
  L3-SIG w0.076: v1(44.16,17.15) 44.92,17.15 45.23,17.46 49.42,17.46 51.33,15.54 54.97,15.54 55.97,14.53 55.97,11.38 56.41,10.95 56.41,9.28 57.07,8.62 58,8.62 58.09,8.71 58.09,9.14 58.18,9.23 58.36,9.23 58.45,9.14 58.45,8.71 58.54,8.62 58.71,8.62 58.8,8.71 58.8,9.14 58.89,9.23 59.07,9.23 59.16,9.14 59.16,8.71 59.25,8.62 59.42,8.62 59.51,8.71 59.51,9.14 59.6,9.23 59.78,9.23 59.87,9.14 59.87,8.71 59.96,8.62 61.3,8.62 62.79,7.13 62.79,6.65 62.72,6.57 61.96,6.57 61.6,6.22 61.6,4.57 61.95,4.22 61.95,3.78 62.15,3.59 v1(62.86,3.59)
  BOTTOM w0.112: v1(62.86,3.59) 62.48,3.59 62.18,3.29 62.18,1.58 JT3.236 ; RB112.2 42.1,18.06 42.12,18.09 42.97,18.09 43.4,17.66 43.78,17.66 44.16,17.28 v1(44.16,17.15)
RMII_BMC_NIC_TXD_1_R: length 9.4
  TOP w0.127: UT7.W12 32.83,17.21 33.17,16.87 v1(33.17,16.85)
  BOTTOM w0.089: 40.23,18.45 39.85,18.83 36.49,18.83 34.92,17.25 33.57,17.25 v1(33.17,16.85)
  BOTTOM w0.104: 40.73,18.06 40.4,18.06 40.23,18.24 40.23,18.45
  BOTTOM w0.112: RB112.1 40.73,18.06
RMII_NIC_BMC_CRS_DV: length 28.7
  TOP w0.127: UT7.AH6 40.71,12.41 40.84,12.27 41.08,12.27 41.27,12.08 41.27,11.69 v1(41.07,11.49)
  L3-SIG w0.076: v1(57.8,4.01) 57.76,4.01 57.75,3.99 57.52,3.99 57.3,3.77 57.3,2.37 57.22,2.29 56.8,2.29 56.72,2.37 56.72,2.62 56.64,2.7 56.49,2.7 56.42,2.62 56.42,2.37 56.34,2.29 48.48,2.29 47.93,2.84 47.93,4.94 47.1,5.77 47.1,6.14 47.28,6.31 47.28,7.26 47.06,7.47 46.1,7.47 45.47,8.11 44.22,8.11 41.7,10.63 41.44,10.63 41.09,10.98 41.09,11.46 v1(41.07,11.49)
  BOTTOM w0.112: v1(57.8,4.01) 57.76,4.04 57.66,4.04 57.18,4.52 RB191.2
